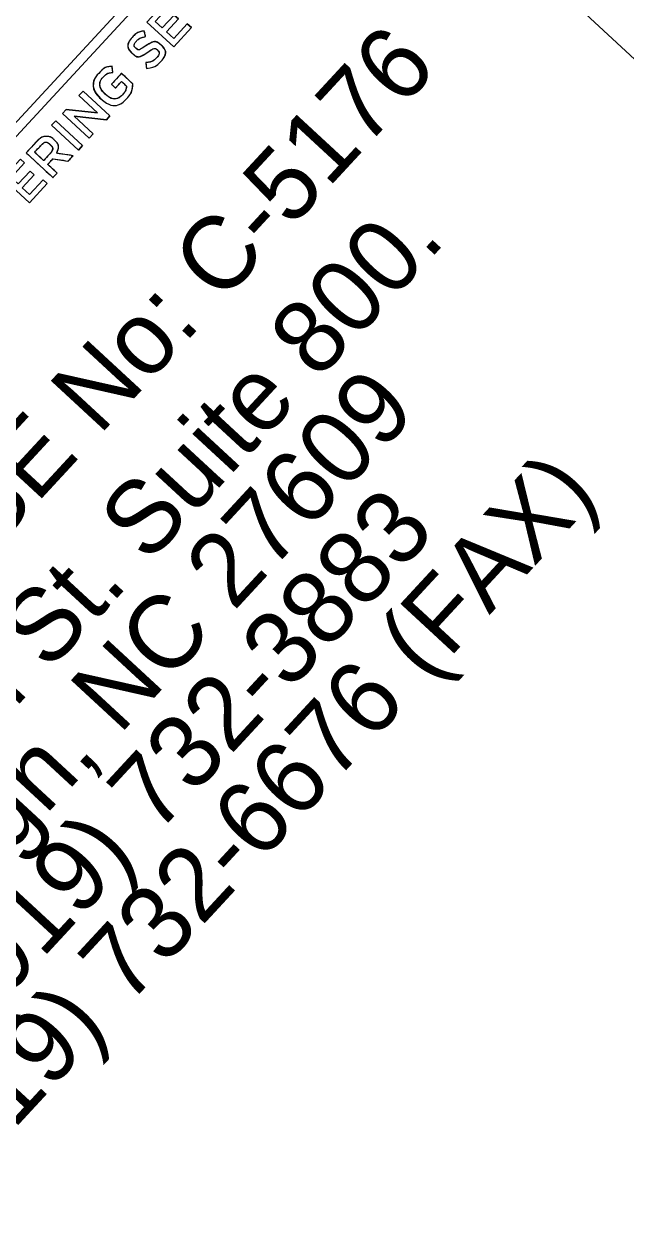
# Model space of a CAD drawing. Extents: x 1768064 to 1770025, y 999327 to 1001342.
# Drawn here: x 1769394.2 to 1769431.7, y 1000999.4 to 1001074.7 of the extents above; entities that cross this region are included whole.
import ezdxf

# ---------------------------------------------------------------- set-up
doc = ezdxf.new("R2010")
doc.units = 0
doc.layers.add('E_NCDOT_Terrain_Model_Spot_Elevation', color=7, linetype='Continuous')
doc.layers.add('P_NCDOT_Horizontal_Alignment_Station_Major_Label', color=7, linetype='Continuous')

msp = doc.modelspace()

# ---------------------------------------------------------------- linework, layer by layer
at = {"layer": 'E_NCDOT_Terrain_Model_Spot_Elevation'}
msp.add_line((1769972.416, 1000573.14), (1769219.739, 1001268.911), dxfattribs=at)
at = {"layer": 'P_NCDOT_Horizontal_Alignment_Station_Major_Label'}
for p, q in [((1769401.794, 1001073.873), (1769401.712, 1001074.228)), ((1769402.764, 1001073.345), (1769402.759, 1001073.349)), ((1769400.945, 1001072.849), (1769400.95, 1001072.844)), ((1769401.183, 1001073.15), (1769401.179, 1001073.154)), ((1769402.528, 1001073.042), (1769402.533, 1001073.037)), ((1769399.756, 1001071.644), (1769399.7, 1001072.027)), ((1769401.797, 1001072.256), (1769401.85, 1001071.893)), ((1769399.278, 1001070.295), (1769399.273, 1001070.299)), ((1769399.005, 1001070), (1769399.01, 1001069.996)), ((1769396.092, 1001067.455), (1769396.087, 1001067.46)), ((1769395.84, 1001067.159), (1769395.845, 1001067.155))]:
    msp.add_line(p, q, dxfattribs=at)
for points in [[(1769409.949, 1001085.219), (1769368.674, 1001040.566), (1769368.23, 1001040.976), (1769409.506, 1001085.629), (1769409.949, 1001085.219)], [(1769409.506, 1001085.629), (1769368.23, 1001040.976), (1769368.674, 1001040.566), (1769409.949, 1001085.219), (1769409.506, 1001085.629)], [(1769401.876, 1001074.779), (1769402.972, 1001075.964), (1769403.234, 1001075.722), (1769402.398, 1001074.817), (1769402.831, 1001074.417), (1769403.573, 1001075.218), (1769403.835, 1001074.976), (1769403.093, 1001074.174), (1769403.541, 1001073.761), (1769404.388, 1001074.677), (1769404.65, 1001074.434), (1769403.543, 1001073.238), (1769401.876, 1001074.779)], [(1769403.543, 1001073.238), (1769404.65, 1001074.434), (1769404.388, 1001074.677), (1769403.541, 1001073.761), (1769403.093, 1001074.174), (1769403.835, 1001074.976), (1769403.573, 1001075.218), (1769402.831, 1001074.417), (1769402.398, 1001074.817), (1769403.234, 1001075.722), (1769402.972, 1001075.964), (1769401.876, 1001074.779), (1769403.543, 1001073.238)], [(1769400.991, 1001070.94), (1769400.291, 1001071.587), (1769399.661, 1001070.906), (1769399.916, 1001070.671), (1769400.294, 1001071.079), (1769400.606, 1001070.791)], [(1769396.612, 1001069.083), (1769396.853, 1001069.344), (1769398.797, 1001069.135), (1769397.644, 1001070.2), (1769397.9, 1001070.477), (1769399.567, 1001068.936), (1769399.349, 1001068.7), (1769397.348, 1001068.915), (1769398.534, 1001067.819), (1769398.279, 1001067.542), (1769396.612, 1001069.083)], [(1769398.279, 1001067.542), (1769398.534, 1001067.819), (1769397.348, 1001068.915), (1769399.349, 1001068.7), (1769399.567, 1001068.936), (1769397.9, 1001070.477), (1769397.644, 1001070.2), (1769398.797, 1001069.135), (1769396.853, 1001069.344), (1769396.612, 1001069.083), (1769398.279, 1001067.542)], [(1769395.937, 1001068.353), (1769396.196, 1001068.633), (1769397.863, 1001067.093), (1769397.604, 1001066.812), (1769395.937, 1001068.353)], [(1769397.604, 1001066.812), (1769397.863, 1001067.093), (1769396.196, 1001068.633), (1769395.937, 1001068.353), (1769397.604, 1001066.812)], [(1769395.012, 1001067.352), (1769394.354, 1001066.64), (1769396.021, 1001065.099), (1769396.28, 1001065.38), (1769395.699, 1001065.917), (1769396.024, 1001066.269), (1769396.968, 1001066.125), (1769397.277, 1001066.458), (1769396.247, 1001066.61)], [(1769395.82, 1001066.568), (1769395.44, 1001066.157), (1769394.88, 1001066.674), (1769395.258, 1001067.083)], [(1769392.897, 1001065.064), (1769393.993, 1001066.25), (1769394.255, 1001066.007), (1769393.419, 1001065.103), (1769393.852, 1001064.702), (1769394.593, 1001065.504), (1769394.855, 1001065.262), (1769394.114, 1001064.46), (1769394.562, 1001064.046), (1769395.409, 1001064.963), (1769395.671, 1001064.72), (1769394.564, 1001063.524), (1769392.897, 1001065.064)], [(1769394.564, 1001063.524), (1769395.671, 1001064.72), (1769395.409, 1001064.963), (1769394.562, 1001064.046), (1769394.114, 1001064.46), (1769394.855, 1001065.262), (1769394.593, 1001065.504), (1769393.852, 1001064.702), (1769393.419, 1001065.103), (1769394.255, 1001066.007), (1769393.993, 1001066.25), (1769392.897, 1001065.064), (1769394.564, 1001063.524)]]:
    msp.add_lwpolyline(points, dxfattribs=at)
for points, degree in [([(1769401.712, 1001074.228), (1769401.426, 1001074.191), (1769401.182, 1001074.075), (1769400.966, 1001073.842), (1769400.673, 1001073.524), (1769400.659, 1001073.113), (1769400.945, 1001072.849)], 3), ([(1769401.85, 1001071.893), (1769401.85, 1001071.893), (1769401.797, 1001072.256), (1769401.797, 1001072.256), (1769402.076, 1001072.281), (1769402.299, 1001072.364), (1769402.48, 1001072.56), (1769402.641, 1001072.734), (1769402.656, 1001072.923), (1769402.533, 1001073.037), (1769402.533, 1001073.037), (1769402.528, 1001073.042), (1769402.528, 1001073.042), (1769402.409, 1001073.152), (1769402.285, 1001073.147), (1769401.94, 1001072.917), (1769401.539, 1001072.655), (1769401.257, 1001072.56), (1769400.95, 1001072.844), (1769400.95, 1001072.844), (1769400.945, 1001072.849), (1769400.945, 1001072.849), (1769400.659, 1001073.113), (1769400.673, 1001073.524), (1769400.966, 1001073.842), (1769401.182, 1001074.075), (1769401.426, 1001074.191), (1769401.712, 1001074.228), (1769401.712, 1001074.228), (1769401.794, 1001073.873), (1769401.794, 1001073.873), (1769401.549, 1001073.832), (1769401.357, 1001073.743), (1769401.221, 1001073.597), (1769401.07, 1001073.433), (1769401.069, 1001073.255), (1769401.179, 1001073.154), (1769401.179, 1001073.154), (1769401.183, 1001073.15), (1769401.183, 1001073.15), (1769401.312, 1001073.031), (1769401.437, 1001073.051), (1769401.798, 1001073.289), (1769402.196, 1001073.548), (1769402.483, 1001073.605), (1769402.759, 1001073.349), (1769402.759, 1001073.349), (1769402.764, 1001073.345), (1769402.764, 1001073.345), (1769403.076, 1001073.057), (1769403.044, 1001072.65), (1769402.734, 1001072.314), (1769402.508, 1001072.069), (1769402.206, 1001071.92), (1769401.85, 1001071.893)], 3), ([(1769401.179, 1001073.154), (1769401.069, 1001073.255), (1769401.07, 1001073.433), (1769401.221, 1001073.597), (1769401.357, 1001073.743), (1769401.549, 1001073.832), (1769401.794, 1001073.873)], 3), ([(1769402.759, 1001073.349), (1769402.483, 1001073.605), (1769402.196, 1001073.548), (1769401.798, 1001073.289), (1769401.437, 1001073.051), (1769401.312, 1001073.031), (1769401.183, 1001073.15)], 3), ([(1769401.85, 1001071.893), (1769402.206, 1001071.92), (1769402.508, 1001072.069), (1769402.734, 1001072.314), (1769403.044, 1001072.65), (1769403.076, 1001073.057), (1769402.764, 1001073.345)], 3), ([(1769400.95, 1001072.844), (1769401.257, 1001072.56), (1769401.539, 1001072.655), (1769401.94, 1001072.917), (1769402.285, 1001073.147), (1769402.409, 1001073.152), (1769402.528, 1001073.042)], 3), ([(1769402.533, 1001073.037), (1769402.656, 1001072.923), (1769402.641, 1001072.734), (1769402.48, 1001072.56), (1769402.299, 1001072.364), (1769402.076, 1001072.281), (1769401.797, 1001072.256)], 3), ([(1769399.01, 1001069.996), (1769399.01, 1001069.996), (1769399.005, 1001070), (1769399.005, 1001070), (1769398.539, 1001070.432), (1769398.46, 1001071.14), (1769398.905, 1001071.622), (1769399.163, 1001071.9), (1769399.402, 1001071.997), (1769399.7, 1001072.027), (1769399.7, 1001072.027), (1769399.756, 1001071.644), (1769399.756, 1001071.644), (1769399.533, 1001071.622), (1769399.352, 1001071.565), (1769399.164, 1001071.362), (1769398.892, 1001071.067), (1769398.954, 1001070.594), (1769399.273, 1001070.299), (1769399.273, 1001070.299), (1769399.278, 1001070.295), (1769399.278, 1001070.295), (1769399.621, 1001069.978), (1769400.073, 1001069.962), (1769400.376, 1001070.288), (1769400.515, 1001070.439), (1769400.592, 1001070.622), (1769400.606, 1001070.791), (1769400.606, 1001070.791), (1769400.294, 1001071.079), (1769400.294, 1001071.079), (1769400.294, 1001071.079), (1769399.916, 1001070.671), (1769399.916, 1001070.671), (1769399.916, 1001070.671), (1769399.661, 1001070.906), (1769399.661, 1001070.906), (1769399.661, 1001070.906), (1769400.291, 1001071.587), (1769400.291, 1001071.587), (1769400.291, 1001071.587), (1769400.991, 1001070.94), (1769400.991, 1001070.94), (1769400.986, 1001070.652), (1769400.896, 1001070.316), (1769400.634, 1001070.033), (1769400.171, 1001069.532), (1769399.496, 1001069.547), (1769399.01, 1001069.996)], 3), ([(1769399.7, 1001072.027), (1769399.402, 1001071.997), (1769399.163, 1001071.9), (1769398.905, 1001071.622), (1769398.46, 1001071.14), (1769398.539, 1001070.432), (1769399.005, 1001070)], 3), ([(1769399.273, 1001070.299), (1769398.954, 1001070.594), (1769398.892, 1001071.067), (1769399.164, 1001071.362), (1769399.352, 1001071.565), (1769399.533, 1001071.622), (1769399.756, 1001071.644)], 3), ([(1769399.01, 1001069.996), (1769399.496, 1001069.547), (1769400.171, 1001069.532), (1769400.634, 1001070.033), (1769400.896, 1001070.316), (1769400.986, 1001070.652), (1769400.991, 1001070.94)], 3), ([(1769400.606, 1001070.791), (1769400.592, 1001070.622), (1769400.515, 1001070.439), (1769400.376, 1001070.288), (1769400.073, 1001069.962), (1769399.621, 1001069.978), (1769399.278, 1001070.295)], 3), ([(1769394.354, 1001066.64), (1769394.354, 1001066.64), (1769395.012, 1001067.352), (1769395.012, 1001067.352), (1769395.198, 1001067.553), (1769395.405, 1001067.654), (1769395.605, 1001067.66), (1769395.774, 1001067.661), (1769395.942, 1001067.594), (1769396.087, 1001067.46), (1769396.087, 1001067.46), (1769396.092, 1001067.455), (1769396.092, 1001067.455), (1769396.366, 1001067.202), (1769396.385, 1001066.893), (1769396.247, 1001066.61), (1769396.247, 1001066.61), (1769397.277, 1001066.458), (1769397.277, 1001066.458), (1769397.277, 1001066.458), (1769396.968, 1001066.125), (1769396.968, 1001066.125), (1769396.968, 1001066.125), (1769396.024, 1001066.269), (1769396.024, 1001066.269), (1769396.024, 1001066.269), (1769395.699, 1001065.917), (1769395.699, 1001065.917), (1769395.699, 1001065.917), (1769396.28, 1001065.38), (1769396.28, 1001065.38), (1769396.28, 1001065.38), (1769396.021, 1001065.099), (1769396.021, 1001065.099), (1769396.021, 1001065.099), (1769394.354, 1001066.64), (1769394.354, 1001066.64)], 3), ([(1769395.82, 1001066.568), (1769396.005, 1001066.769), (1769396.014, 1001066.998), (1769395.845, 1001067.155), (1769395.845, 1001067.155), (1769395.84, 1001067.159), (1769395.84, 1001067.159), (1769395.662, 1001067.324), (1769395.45, 1001067.291), (1769395.258, 1001067.083), (1769395.258, 1001067.083), (1769394.88, 1001066.674), (1769394.88, 1001066.674), (1769394.88, 1001066.674), (1769395.44, 1001066.157), (1769395.44, 1001066.157), (1769395.44, 1001066.157), (1769395.82, 1001066.568), (1769395.82, 1001066.568)], 3), ([(1769396.087, 1001067.46), (1769395.942, 1001067.594), (1769395.774, 1001067.661), (1769395.605, 1001067.66), (1769395.405, 1001067.654), (1769395.198, 1001067.553), (1769395.012, 1001067.352)], 3), ([(1769395.258, 1001067.083), (1769395.45, 1001067.291), (1769395.662, 1001067.324), (1769395.84, 1001067.159)], 2), ([(1769396.247, 1001066.61), (1769396.385, 1001066.893), (1769396.366, 1001067.202), (1769396.092, 1001067.455)], 2), ([(1769395.845, 1001067.155), (1769396.014, 1001066.998), (1769396.005, 1001066.769), (1769395.82, 1001066.568)], 2)]:
    msp.add_open_spline(points, degree=degree, dxfattribs=at)

# ---------------------------------------------------------------- texts
for s, p in [('NC FIRM LICENSE No: C-5176', (1769361.678, 1001008.716)), ('1000 Social St. Suite 800.', (1769372.975, 1001009.653)), ('Raleigh, NC 27609', (1769383.831, 1001012.68)), ('(919) 732-6676 (FAX)', (1769389.866, 1001001.773)), ('(919) 732-3883', (1769391.662, 1001012.433))]:
    msp.add_text(s, height=4.55564, rotation=47.25123, dxfattribs=at).set_placement(p)

doc.saveas('drawing.dxf')
